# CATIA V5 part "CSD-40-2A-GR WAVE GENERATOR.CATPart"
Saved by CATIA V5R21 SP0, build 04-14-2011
Part number: CSD-40-2A-GR WAVE GENERATOR
Revision: ANY
Definition: UNKNOWN
Nomenclature: CSD-40-2A-GR WAVE GENERATOR
Source: Unknown
Bounding box of the stored display mesh (mm): x 0 to 10.3, y -35.429 to 35.5, z -35.5 to 35.5
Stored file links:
  C:\Users\MIRCEA\Desktop\PRRO\CATIAV5\CSD-40-2A-GR WAVE GENERATOR.CATPart
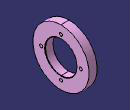
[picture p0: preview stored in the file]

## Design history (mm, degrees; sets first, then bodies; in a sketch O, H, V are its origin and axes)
Body1 "Chamfer1" (main body)
  Solid1: solid without history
